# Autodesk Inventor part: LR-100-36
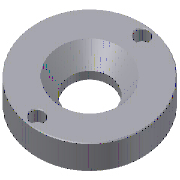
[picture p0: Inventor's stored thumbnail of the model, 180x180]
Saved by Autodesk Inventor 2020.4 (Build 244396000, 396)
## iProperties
Created: 2019-01
Part Number: LR-100-36
Material: S 45 C
Description: Locating Ring
Document SubType Name: Modeling
Designer: mel
Standard Revision: 1
Manufacturer: LKM
Language: fr-FR
Size Designation: LR-100-36
Categories: <MemberInstance><Categories><Category DisplayName="Moule" InternalName="349578f2-f4d4-4954-8c09-8e99297a61c0" Mnemonic="MOLD"><Category DisplayName="Centrage" I
Mass: 93.9026 g
Surface Area: 200.182 cm^2
Volume: 93.9026 cm^3
Density: 7.85 g/cm^3
Appearance: Aluminium - Noir
IsCustomPart: 1
Author: mel
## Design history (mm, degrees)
sketch "Sketch1"
  geometry: L1 (0, -3)-(0, 18) reference; L2 (28, 15)-(18, 5); L3 (18, 5)-(18, 0); L4 (18, 0)-(50, 0); L5 (50, 0)-(50, 15); L6 (50, 15)-(28, 15); 1 further point
  constraints: 10 end point, 2 horizontal, 2 vertical, 1 point on line
  dimensions: "d0" = 36 diameter of L3 L1 (= d_); "d1" = 45 deg angle of L1 L2; "d2" = 15 distance between parallel lines of L4 L6 (= T_); "d3" = 100 diameter of L5 L1 (= D); "d4" = 5 distance from line of L4 L2.end
revolve "Revolution1" sketch "Sketch1" stored, may be unused: angle "d5" = 90 deg
sketch "Sketch2"
  geometry: 3 further points
  constraints: 2 vertical alignment
  dimensions: "d26" = 42.5 distance of point (0, 0) point (0, 42.5) (= 0.5 x P); "d27" = 42.5 distance of point (0, -42.5) point (0, 0) (= 0.5 x P)
hole "Hole1" sketch "Sketch2" diameter "d7" = 6.6; stored, may be unused: countersink angle "d11" = 90 deg, drill point angle "d13" = 0 deg; dims "d8" = 6, "d9" = 11, "d10" = 6.8, "d12" = 15 (= T_)
hole "Hole2" sketch "Sketch2" diameter "d28" = 6.6; stored, may be unused: countersink angle "d32" = 90 deg, drill point angle "d34" = 0 deg; dims "d29" = 6, "d30" = 11, "d31" = 6.8, "d33" = 15 (= T_)
chamfer "Chamfer1" distance "d14" = 0.5; stored, may be unused: second distance "d15" = 2, angle "d16" = 45 deg
sketch "Sketch3"
  geometry: L1 (0, -3)-(0, 18) reference; L2 (0, 0)-(50, 0); L3 (50, 0)-(50, 15); L4 (50, 15)-(0, 15); L5 (0, 15)-(0, 0)
  constraints: 8 end point, 2 parallel, 1 horizontal, 1 perpendicular
  dimensions: "d20" = 100 diameter of L3 L1 (= D_CS); "d21" = 15 distance between parallel lines of L2 L4 (= T_CS)
feature "RevolutionSrf1" sketch "Sketch3" dims angle "d22" = 90 deg
body "Solid1"
body "Srf1"
other parameters: "D" = 100 [user parameter; used in 1 equation term], "d_" = 36 [user parameter; used in 1 equation term], "P" = 85 [user parameter; used in 2 equation terms], "T_" = 15 [user parameter; used in 3 equation terms], "D_CS" = 100 [user parameter; used in 1 equation term], "T_CS" = 15 [user parameter; used in 1 equation term], "d23" = 0, "d24" = 0, "d25" = 0
